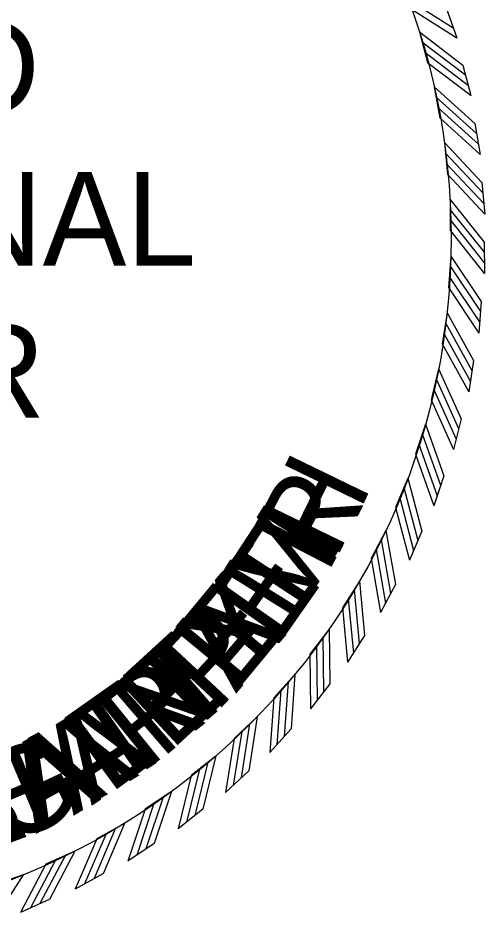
# Model space of a CAD drawing. Extents: x 18 to 14744716, y -5 to 1829144.
# Drawn here: x 17.7969 to 17.8525, y 10.8241 to 10.9324 of the extents above; entities that cross this region are included whole.
import ezdxf

# ---------------------------------------------------------------- set-up
doc = ezdxf.new("R2010")
doc.units = 0
for name, color, linetype in [('B_StampHSS', 7, 'Continuous'), ('B_StampJSB', 7, 'Continuous'), ('B_StampSCR', 7, 'Continuous'), ('B_StampSFH', 7, 'Continuous')]:
    doc.layers.add(name, color=color, linetype=linetype)

msp = doc.modelspace()

# ---------------------------------------------------------------- linework, layer by layer
at = {"layer": 'B_StampHSS'}
for p, q in [((17.84791, 10.93362), (17.84917, 10.93006)), ((17.84472, 10.93075), (17.84568, 10.9271)), ((17.8499, 10.9268), (17.85086, 10.92315)), ((17.84648, 10.9242), (17.84714, 10.92048)), ((17.85133, 10.91983), (17.85198, 10.91612)), ((17.8477, 10.91753), (17.84805, 10.91377)), ((17.85217, 10.91278), (17.85252, 10.90902)), ((17.84837, 10.91078), (17.8484, 10.90701)), ((17.85243, 10.90568), (17.85246, 10.90191)), ((17.84847, 10.904), (17.8482, 10.90023)), ((17.8521, 10.89858), (17.85182, 10.89482)), ((17.84802, 10.89724), (17.84743, 10.8935)), ((17.85118, 10.89153), (17.8506, 10.88781)), ((17.84701, 10.89053), (17.84611, 10.88686)), ((17.84545, 10.88393), (17.84425, 10.88035)), ((17.84969, 10.88458), (17.8488, 10.88092)), ((17.84334, 10.87748), (17.84186, 10.87401)), ((17.84763, 10.87778), (17.84643, 10.87421)), ((17.84072, 10.87123), (17.83895, 10.86789)), ((17.84501, 10.87117), (17.84353, 10.86771)), ((17.83758, 10.86522), (17.83554, 10.86203)), ((17.84186, 10.86481), (17.84009, 10.86147)), ((17.83396, 10.85948), (17.83167, 10.85648)), ((17.83819, 10.85872), (17.83615, 10.85555)), ((17.82988, 10.85406), (17.82735, 10.85126)), ((17.83403, 10.85296), (17.83174, 10.84996)), ((17.82536, 10.849), (17.82261, 10.84642)), ((17.82941, 10.84756), (17.82688, 10.84476)), ((17.82045, 10.84433), (17.81749, 10.84199)), ((17.82436, 10.84256), (17.82161, 10.83998)), ((17.81516, 10.84009), (17.81202, 10.83799)), ((17.81891, 10.83799), (17.81596, 10.83565)), ((17.80954, 10.83629), (17.80624, 10.83446)), ((17.81311, 10.83389), (17.80997, 10.8318)), ((17.80363, 10.83297), (17.80018, 10.83142)), ((17.79746, 10.83015), (17.7939, 10.82889)), ((17.80698, 10.83029), (17.80368, 10.82846)), ((17.80058, 10.8272), (17.79714, 10.82565))]:
    msp.add_line(p, q, dxfattribs=at)
for points in [[(17.84327, 10.93476), (17.84876, 10.93125)], [(17.84367, 10.93357), (17.84917, 10.93006)], [(17.84471, 10.93076), (17.8499, 10.9268)], [(17.84501, 10.92958), (17.8502, 10.92563)], [(17.84537, 10.92832), (17.85056, 10.92437)], [(17.84568, 10.9271), (17.85087, 10.92315)], [(17.84648, 10.92421), (17.85132, 10.91984)], [(17.84668, 10.92301), (17.85152, 10.91864)], [(17.84693, 10.92173), (17.85178, 10.91736)], [(17.84714, 10.92049), (17.85198, 10.91612)], [(17.8477, 10.91754), (17.85217, 10.91278)], [(17.8478, 10.91633), (17.85227, 10.91157)], [(17.84795, 10.91503), (17.85241, 10.91027)], [(17.84805, 10.91377), (17.85252, 10.90902)], [(17.84836, 10.91079), (17.85242, 10.90568)], [(17.84836, 10.90957), (17.85242, 10.90447)], [(17.84841, 10.90827), (17.85246, 10.90316)], [(17.84841, 10.90701), (17.85246, 10.9019)], [(17.84847, 10.90401), (17.85209, 10.89858)], [(17.84837, 10.9028), (17.85199, 10.89737)], [(17.8483, 10.90149), (17.85193, 10.89607)], [(17.8482, 10.90024), (17.85182, 10.89481)], [(17.84802, 10.89724), (17.85118, 10.89154)], [(17.84782, 10.89604), (17.85098, 10.89034)], [(17.84764, 10.89475), (17.8508, 10.88904)], [(17.84744, 10.89351), (17.8506, 10.8878)], [(17.84701, 10.89054), (17.84969, 10.88459)], [(17.84671, 10.88936), (17.84939, 10.88341)], [(17.84643, 10.88808), (17.84911, 10.88213)], [(17.84612, 10.88686), (17.8488, 10.88092)], [(17.84544, 10.88394), (17.84762, 10.87779)], [(17.84505, 10.88279), (17.84723, 10.87664)], [(17.84466, 10.88154), (17.84684, 10.87539)], [(17.84426, 10.88035), (17.84644, 10.8742)], [(17.84334, 10.87749), (17.84501, 10.87118)], [(17.84285, 10.87638), (17.84452, 10.87007)], [(17.84237, 10.87516), (17.84403, 10.86885)], [(17.84186, 10.87401), (17.84353, 10.8677)], [(17.84072, 10.87124), (17.84185, 10.86481)], [(17.84014, 10.87017), (17.84128, 10.86375)], [(17.83955, 10.869), (17.84069, 10.86257)], [(17.83895, 10.86789), (17.84009, 10.86147)], [(17.83758, 10.86522), (17.83819, 10.85873)], [(17.83692, 10.86421), (17.83752, 10.85771)], [(17.83624, 10.86309), (17.83684, 10.85659)], [(17.83555, 10.86204), (17.83615, 10.85554)], [(17.83396, 10.85949), (17.83403, 10.85296)], [(17.83322, 10.85853), (17.83328, 10.85201)], [(17.83167, 10.85648), (17.83174, 10.84996)], [(17.83244, 10.85747), (17.83251, 10.85095)], [(17.82906, 10.85318), (17.82859, 10.84667)], [(17.82988, 10.85407), (17.82941, 10.84756)], [(17.8282, 10.85219), (17.82773, 10.84568)], [(17.82735, 10.85126), (17.82688, 10.84476)], [(17.82537, 10.84901), (17.82436, 10.84257)], [(17.82447, 10.84819), (17.82347, 10.84174)], [(17.82354, 10.84727), (17.82253, 10.84083)], [(17.82261, 10.84642), (17.82161, 10.83998)], [(17.81949, 10.84359), (17.81795, 10.83725)], [(17.82045, 10.84434), (17.81891, 10.838)], [(17.81848, 10.84276), (17.81695, 10.83642)], [(17.81749, 10.84199), (17.81596, 10.83565)], [(17.81415, 10.83943), (17.81209, 10.83324)], [(17.81516, 10.84009), (17.81311, 10.8339)], [(17.81307, 10.83868), (17.81102, 10.83249)], [(17.81202, 10.83799), (17.80997, 10.8318)], [(17.80954, 10.83629), (17.80699, 10.83029)], [(17.80735, 10.83506), (17.80479, 10.82906)], [(17.80848, 10.83572), (17.80592, 10.82972)], [(17.80624, 10.83446), (17.80368, 10.82846)], [(17.80363, 10.83297), (17.80059, 10.8272)], [(17.80134, 10.83192), (17.79829, 10.82615)], [(17.80252, 10.83249), (17.79947, 10.82672)], [(17.80019, 10.83142), (17.79714, 10.82565)], [(17.79746, 10.83015), (17.79395, 10.82465)]]:
    msp.add_lwpolyline(points, dxfattribs=at)
at = {"layer": 'B_StampJSB'}
for p, q in [((17.84791, 10.93362), (17.84917, 10.93006)), ((17.84472, 10.93075), (17.84568, 10.9271)), ((17.8499, 10.9268), (17.85086, 10.92315)), ((17.84648, 10.9242), (17.84714, 10.92048)), ((17.85133, 10.91983), (17.85198, 10.91612)), ((17.8477, 10.91753), (17.84805, 10.91377)), ((17.85217, 10.91278), (17.85252, 10.90902)), ((17.84837, 10.91078), (17.8484, 10.90701)), ((17.85243, 10.90568), (17.85246, 10.90191)), ((17.84847, 10.904), (17.8482, 10.90023)), ((17.8521, 10.89858), (17.85182, 10.89482)), ((17.84802, 10.89724), (17.84743, 10.8935)), ((17.85118, 10.89153), (17.8506, 10.88781)), ((17.84701, 10.89053), (17.84611, 10.88686)), ((17.84545, 10.88393), (17.84425, 10.88035)), ((17.84969, 10.88458), (17.8488, 10.88092)), ((17.84334, 10.87748), (17.84186, 10.87401)), ((17.84763, 10.87778), (17.84643, 10.87421)), ((17.84072, 10.87123), (17.83895, 10.86789)), ((17.84501, 10.87117), (17.84353, 10.86771)), ((17.83758, 10.86522), (17.83554, 10.86203)), ((17.84186, 10.86481), (17.84009, 10.86147)), ((17.83396, 10.85948), (17.83167, 10.85648)), ((17.83819, 10.85872), (17.83615, 10.85555)), ((17.82988, 10.85406), (17.82735, 10.85126)), ((17.83403, 10.85296), (17.83174, 10.84996)), ((17.82536, 10.849), (17.82261, 10.84642)), ((17.82941, 10.84756), (17.82688, 10.84476)), ((17.82045, 10.84433), (17.81749, 10.84199)), ((17.82436, 10.84256), (17.82161, 10.83998)), ((17.81516, 10.84009), (17.81202, 10.83799)), ((17.81891, 10.83799), (17.81596, 10.83565)), ((17.80954, 10.83629), (17.80624, 10.83446)), ((17.81311, 10.83389), (17.80997, 10.8318)), ((17.80363, 10.83297), (17.80018, 10.83142)), ((17.79746, 10.83015), (17.7939, 10.82889)), ((17.80698, 10.83029), (17.80368, 10.82846)), ((17.80058, 10.8272), (17.79714, 10.82565))]:
    msp.add_line(p, q, dxfattribs=at)
for points in [[(17.84327, 10.93476), (17.84876, 10.93125)], [(17.84367, 10.93357), (17.84917, 10.93006)], [(17.84471, 10.93076), (17.8499, 10.9268)], [(17.84501, 10.92958), (17.8502, 10.92563)], [(17.84537, 10.92832), (17.85056, 10.92437)], [(17.84568, 10.9271), (17.85087, 10.92315)], [(17.84648, 10.92421), (17.85132, 10.91984)], [(17.84668, 10.92301), (17.85152, 10.91864)], [(17.84693, 10.92173), (17.85178, 10.91736)], [(17.84714, 10.92049), (17.85198, 10.91612)], [(17.8477, 10.91754), (17.85217, 10.91278)], [(17.8478, 10.91633), (17.85227, 10.91157)], [(17.84795, 10.91503), (17.85241, 10.91027)], [(17.84805, 10.91377), (17.85252, 10.90902)], [(17.84836, 10.91079), (17.85242, 10.90568)], [(17.84836, 10.90957), (17.85242, 10.90447)], [(17.84841, 10.90827), (17.85246, 10.90316)], [(17.84841, 10.90701), (17.85246, 10.9019)], [(17.84847, 10.90401), (17.85209, 10.89858)], [(17.84837, 10.9028), (17.85199, 10.89737)], [(17.8483, 10.90149), (17.85193, 10.89607)], [(17.8482, 10.90024), (17.85182, 10.89481)], [(17.84802, 10.89724), (17.85118, 10.89154)], [(17.84782, 10.89604), (17.85098, 10.89034)], [(17.84764, 10.89475), (17.8508, 10.88904)], [(17.84744, 10.89351), (17.8506, 10.8878)], [(17.84701, 10.89054), (17.84969, 10.88459)], [(17.84671, 10.88936), (17.84939, 10.88341)], [(17.84643, 10.88808), (17.84911, 10.88213)], [(17.84612, 10.88686), (17.8488, 10.88092)], [(17.84544, 10.88394), (17.84762, 10.87779)], [(17.84505, 10.88279), (17.84723, 10.87664)], [(17.84466, 10.88154), (17.84684, 10.87539)], [(17.84426, 10.88035), (17.84644, 10.8742)], [(17.84334, 10.87749), (17.84501, 10.87118)], [(17.84285, 10.87638), (17.84452, 10.87007)], [(17.84237, 10.87516), (17.84403, 10.86885)], [(17.84186, 10.87401), (17.84353, 10.8677)], [(17.84072, 10.87124), (17.84185, 10.86481)], [(17.84014, 10.87017), (17.84128, 10.86375)], [(17.83955, 10.869), (17.84069, 10.86257)], [(17.83895, 10.86789), (17.84009, 10.86147)], [(17.83758, 10.86522), (17.83819, 10.85873)], [(17.83692, 10.86421), (17.83752, 10.85771)], [(17.83624, 10.86309), (17.83684, 10.85659)], [(17.83555, 10.86204), (17.83615, 10.85554)], [(17.83396, 10.85949), (17.83403, 10.85296)], [(17.83322, 10.85853), (17.83328, 10.85201)], [(17.83167, 10.85648), (17.83174, 10.84996)], [(17.83244, 10.85747), (17.83251, 10.85095)], [(17.82906, 10.85318), (17.82859, 10.84667)], [(17.82988, 10.85407), (17.82941, 10.84756)], [(17.8282, 10.85219), (17.82773, 10.84568)], [(17.82735, 10.85126), (17.82688, 10.84476)], [(17.82537, 10.84901), (17.82436, 10.84257)], [(17.82447, 10.84819), (17.82347, 10.84174)], [(17.82354, 10.84727), (17.82253, 10.84083)], [(17.82261, 10.84642), (17.82161, 10.83998)], [(17.81949, 10.84359), (17.81795, 10.83725)], [(17.82045, 10.84434), (17.81891, 10.838)], [(17.81848, 10.84276), (17.81695, 10.83642)], [(17.81749, 10.84199), (17.81596, 10.83565)], [(17.81415, 10.83943), (17.81209, 10.83324)], [(17.81516, 10.84009), (17.81311, 10.8339)], [(17.81307, 10.83868), (17.81102, 10.83249)], [(17.81202, 10.83799), (17.80997, 10.8318)], [(17.80954, 10.83629), (17.80699, 10.83029)], [(17.80735, 10.83506), (17.80479, 10.82906)], [(17.80848, 10.83572), (17.80592, 10.82972)], [(17.80624, 10.83446), (17.80368, 10.82846)], [(17.80363, 10.83297), (17.80059, 10.8272)], [(17.80134, 10.83192), (17.79829, 10.82615)], [(17.80252, 10.83249), (17.79947, 10.82672)], [(17.80019, 10.83142), (17.79714, 10.82565)], [(17.79746, 10.83015), (17.79395, 10.82465)]]:
    msp.add_lwpolyline(points, dxfattribs=at)
msp.add_circle((17.76645, 10.90612), 0.08205, dxfattribs=at)
at = {"layer": 'B_StampSCR'}
for p, q in [((17.84791, 10.93362), (17.84917, 10.93006)), ((17.84472, 10.93075), (17.84568, 10.9271)), ((17.8499, 10.9268), (17.85086, 10.92315)), ((17.84648, 10.9242), (17.84714, 10.92048)), ((17.85133, 10.91983), (17.85198, 10.91612)), ((17.8477, 10.91753), (17.84805, 10.91377)), ((17.85217, 10.91278), (17.85252, 10.90902)), ((17.84837, 10.91078), (17.8484, 10.90701)), ((17.85243, 10.90568), (17.85246, 10.90191)), ((17.84847, 10.904), (17.8482, 10.90023)), ((17.8521, 10.89858), (17.85182, 10.89482)), ((17.84802, 10.89724), (17.84743, 10.8935)), ((17.85118, 10.89153), (17.8506, 10.88781)), ((17.84701, 10.89053), (17.84611, 10.88686)), ((17.84545, 10.88393), (17.84425, 10.88035)), ((17.84969, 10.88458), (17.8488, 10.88092)), ((17.84334, 10.87748), (17.84186, 10.87401)), ((17.84763, 10.87778), (17.84643, 10.87421)), ((17.84072, 10.87123), (17.83895, 10.86789)), ((17.84501, 10.87117), (17.84353, 10.86771)), ((17.83758, 10.86522), (17.83554, 10.86203)), ((17.84186, 10.86481), (17.84009, 10.86147)), ((17.83396, 10.85948), (17.83167, 10.85648)), ((17.83819, 10.85872), (17.83615, 10.85555)), ((17.82988, 10.85406), (17.82735, 10.85126)), ((17.83403, 10.85296), (17.83174, 10.84996)), ((17.82536, 10.849), (17.82261, 10.84642)), ((17.82941, 10.84756), (17.82688, 10.84476)), ((17.82045, 10.84433), (17.81749, 10.84199)), ((17.82436, 10.84256), (17.82161, 10.83998)), ((17.81516, 10.84009), (17.81202, 10.83799)), ((17.81891, 10.83799), (17.81596, 10.83565)), ((17.80954, 10.83629), (17.80624, 10.83446)), ((17.81311, 10.83389), (17.80997, 10.8318)), ((17.80363, 10.83297), (17.80018, 10.83142)), ((17.79746, 10.83015), (17.7939, 10.82889)), ((17.80698, 10.83029), (17.80368, 10.82846)), ((17.80058, 10.8272), (17.79714, 10.82565))]:
    msp.add_line(p, q, dxfattribs=at)
for points in [[(17.84327, 10.93476), (17.84876, 10.93125)], [(17.84367, 10.93357), (17.84917, 10.93006)], [(17.84471, 10.93076), (17.8499, 10.9268)], [(17.84501, 10.92958), (17.8502, 10.92563)], [(17.84537, 10.92832), (17.85056, 10.92437)], [(17.84568, 10.9271), (17.85087, 10.92315)], [(17.84648, 10.92421), (17.85132, 10.91984)], [(17.84668, 10.92301), (17.85152, 10.91864)], [(17.84693, 10.92173), (17.85178, 10.91736)], [(17.84714, 10.92049), (17.85198, 10.91612)], [(17.8477, 10.91754), (17.85217, 10.91278)], [(17.8478, 10.91633), (17.85227, 10.91157)], [(17.84795, 10.91503), (17.85241, 10.91027)], [(17.84805, 10.91377), (17.85252, 10.90902)], [(17.84836, 10.91079), (17.85242, 10.90568)], [(17.84836, 10.90957), (17.85242, 10.90447)], [(17.84841, 10.90827), (17.85246, 10.90316)], [(17.84841, 10.90701), (17.85246, 10.9019)], [(17.84847, 10.90401), (17.85209, 10.89858)], [(17.84837, 10.9028), (17.85199, 10.89737)], [(17.8483, 10.90149), (17.85193, 10.89607)], [(17.8482, 10.90024), (17.85182, 10.89481)], [(17.84802, 10.89724), (17.85118, 10.89154)], [(17.84782, 10.89604), (17.85098, 10.89034)], [(17.84764, 10.89475), (17.8508, 10.88904)], [(17.84744, 10.89351), (17.8506, 10.8878)], [(17.84701, 10.89054), (17.84969, 10.88459)], [(17.84671, 10.88936), (17.84939, 10.88341)], [(17.84643, 10.88808), (17.84911, 10.88213)], [(17.84612, 10.88686), (17.8488, 10.88092)], [(17.84544, 10.88394), (17.84762, 10.87779)], [(17.84505, 10.88279), (17.84723, 10.87664)], [(17.84466, 10.88154), (17.84684, 10.87539)], [(17.84426, 10.88035), (17.84644, 10.8742)], [(17.84334, 10.87749), (17.84501, 10.87118)], [(17.84285, 10.87638), (17.84452, 10.87007)], [(17.84237, 10.87516), (17.84403, 10.86885)], [(17.84186, 10.87401), (17.84353, 10.8677)], [(17.84072, 10.87124), (17.84185, 10.86481)], [(17.84014, 10.87017), (17.84128, 10.86375)], [(17.83955, 10.869), (17.84069, 10.86257)], [(17.83895, 10.86789), (17.84009, 10.86147)], [(17.83758, 10.86522), (17.83819, 10.85873)], [(17.83692, 10.86421), (17.83752, 10.85771)], [(17.83624, 10.86309), (17.83684, 10.85659)], [(17.83555, 10.86204), (17.83615, 10.85554)], [(17.83396, 10.85949), (17.83403, 10.85296)], [(17.83322, 10.85853), (17.83328, 10.85201)], [(17.83167, 10.85648), (17.83174, 10.84996)], [(17.83244, 10.85747), (17.83251, 10.85095)], [(17.82906, 10.85318), (17.82859, 10.84667)], [(17.82988, 10.85407), (17.82941, 10.84756)], [(17.8282, 10.85219), (17.82773, 10.84568)], [(17.82735, 10.85126), (17.82688, 10.84476)], [(17.82537, 10.84901), (17.82436, 10.84257)], [(17.82447, 10.84819), (17.82347, 10.84174)], [(17.82354, 10.84727), (17.82253, 10.84083)], [(17.82261, 10.84642), (17.82161, 10.83998)], [(17.81949, 10.84359), (17.81795, 10.83725)], [(17.82045, 10.84434), (17.81891, 10.838)], [(17.81848, 10.84276), (17.81695, 10.83642)], [(17.81749, 10.84199), (17.81596, 10.83565)], [(17.81415, 10.83943), (17.81209, 10.83324)], [(17.81516, 10.84009), (17.81311, 10.8339)], [(17.81307, 10.83868), (17.81102, 10.83249)], [(17.81202, 10.83799), (17.80997, 10.8318)], [(17.80954, 10.83629), (17.80699, 10.83029)], [(17.80735, 10.83506), (17.80479, 10.82906)], [(17.80848, 10.83572), (17.80592, 10.82972)], [(17.80624, 10.83446), (17.80368, 10.82846)], [(17.80363, 10.83297), (17.80059, 10.8272)], [(17.80134, 10.83192), (17.79829, 10.82615)], [(17.80252, 10.83249), (17.79947, 10.82672)], [(17.80019, 10.83142), (17.79714, 10.82565)], [(17.79746, 10.83015), (17.79395, 10.82465)]]:
    msp.add_lwpolyline(points, dxfattribs=at)
at = {"layer": 'B_StampSFH'}
for p, q in [((17.84791, 10.93362), (17.84917, 10.93006)), ((17.84472, 10.93075), (17.84568, 10.9271)), ((17.8499, 10.9268), (17.85086, 10.92315)), ((17.84648, 10.9242), (17.84714, 10.92048)), ((17.85133, 10.91983), (17.85198, 10.91612)), ((17.8477, 10.91753), (17.84805, 10.91377)), ((17.85217, 10.91278), (17.85252, 10.90902)), ((17.84837, 10.91078), (17.8484, 10.90701)), ((17.85243, 10.90568), (17.85246, 10.90191)), ((17.84847, 10.904), (17.8482, 10.90023)), ((17.8521, 10.89858), (17.85182, 10.89482)), ((17.84802, 10.89724), (17.84743, 10.8935)), ((17.85118, 10.89153), (17.8506, 10.88781)), ((17.84701, 10.89053), (17.84611, 10.88686)), ((17.84545, 10.88393), (17.84425, 10.88035)), ((17.84969, 10.88458), (17.8488, 10.88092)), ((17.84334, 10.87748), (17.84186, 10.87401)), ((17.84763, 10.87778), (17.84643, 10.87421)), ((17.84072, 10.87123), (17.83895, 10.86789)), ((17.84501, 10.87117), (17.84353, 10.86771)), ((17.83758, 10.86522), (17.83554, 10.86203)), ((17.84186, 10.86481), (17.84009, 10.86147)), ((17.83396, 10.85948), (17.83167, 10.85648)), ((17.83819, 10.85872), (17.83615, 10.85555)), ((17.82988, 10.85406), (17.82735, 10.85126)), ((17.83403, 10.85296), (17.83174, 10.84996)), ((17.82536, 10.849), (17.82261, 10.84642)), ((17.82941, 10.84756), (17.82688, 10.84476)), ((17.82045, 10.84433), (17.81749, 10.84199)), ((17.82436, 10.84256), (17.82161, 10.83998)), ((17.81516, 10.84009), (17.81202, 10.83799)), ((17.81891, 10.83799), (17.81596, 10.83565)), ((17.80954, 10.83629), (17.80624, 10.83446)), ((17.81311, 10.83389), (17.80997, 10.8318)), ((17.80363, 10.83297), (17.80018, 10.83142)), ((17.79746, 10.83015), (17.7939, 10.82889)), ((17.80698, 10.83029), (17.80368, 10.82846)), ((17.80058, 10.8272), (17.79714, 10.82565))]:
    msp.add_line(p, q, dxfattribs=at)
for points in [[(17.84327, 10.93476), (17.84876, 10.93125)], [(17.84367, 10.93357), (17.84917, 10.93006)], [(17.84471, 10.93076), (17.8499, 10.9268)], [(17.84501, 10.92958), (17.8502, 10.92563)], [(17.84537, 10.92832), (17.85056, 10.92437)], [(17.84568, 10.9271), (17.85087, 10.92315)], [(17.84648, 10.92421), (17.85132, 10.91984)], [(17.84668, 10.92301), (17.85152, 10.91864)], [(17.84693, 10.92173), (17.85178, 10.91736)], [(17.84714, 10.92049), (17.85198, 10.91612)], [(17.8477, 10.91754), (17.85217, 10.91278)], [(17.8478, 10.91633), (17.85227, 10.91157)], [(17.84795, 10.91503), (17.85241, 10.91027)], [(17.84805, 10.91377), (17.85252, 10.90902)], [(17.84836, 10.91079), (17.85242, 10.90568)], [(17.84836, 10.90957), (17.85242, 10.90447)], [(17.84841, 10.90827), (17.85246, 10.90316)], [(17.84841, 10.90701), (17.85246, 10.9019)], [(17.84847, 10.90401), (17.85209, 10.89858)], [(17.84837, 10.9028), (17.85199, 10.89737)], [(17.8483, 10.90149), (17.85193, 10.89607)], [(17.8482, 10.90024), (17.85182, 10.89481)], [(17.84802, 10.89724), (17.85118, 10.89154)], [(17.84782, 10.89604), (17.85098, 10.89034)], [(17.84764, 10.89475), (17.8508, 10.88904)], [(17.84744, 10.89351), (17.8506, 10.8878)], [(17.84701, 10.89054), (17.84969, 10.88459)], [(17.84671, 10.88936), (17.84939, 10.88341)], [(17.84643, 10.88808), (17.84911, 10.88213)], [(17.84612, 10.88686), (17.8488, 10.88092)], [(17.84544, 10.88394), (17.84762, 10.87779)], [(17.84505, 10.88279), (17.84723, 10.87664)], [(17.84466, 10.88154), (17.84684, 10.87539)], [(17.84426, 10.88035), (17.84644, 10.8742)], [(17.84334, 10.87749), (17.84501, 10.87118)], [(17.84285, 10.87638), (17.84452, 10.87007)], [(17.84237, 10.87516), (17.84403, 10.86885)], [(17.84186, 10.87401), (17.84353, 10.8677)], [(17.84072, 10.87124), (17.84185, 10.86481)], [(17.84014, 10.87017), (17.84128, 10.86375)], [(17.83955, 10.869), (17.84069, 10.86257)], [(17.83895, 10.86789), (17.84009, 10.86147)], [(17.83758, 10.86522), (17.83819, 10.85873)], [(17.83692, 10.86421), (17.83752, 10.85771)], [(17.83624, 10.86309), (17.83684, 10.85659)], [(17.83555, 10.86204), (17.83615, 10.85554)], [(17.83396, 10.85949), (17.83403, 10.85296)], [(17.83322, 10.85853), (17.83328, 10.85201)], [(17.83167, 10.85648), (17.83174, 10.84996)], [(17.83244, 10.85747), (17.83251, 10.85095)], [(17.82906, 10.85318), (17.82859, 10.84667)], [(17.82988, 10.85407), (17.82941, 10.84756)], [(17.8282, 10.85219), (17.82773, 10.84568)], [(17.82735, 10.85126), (17.82688, 10.84476)], [(17.82537, 10.84901), (17.82436, 10.84257)], [(17.82447, 10.84819), (17.82347, 10.84174)], [(17.82354, 10.84727), (17.82253, 10.84083)], [(17.82261, 10.84642), (17.82161, 10.83998)], [(17.81949, 10.84359), (17.81795, 10.83725)], [(17.82045, 10.84434), (17.81891, 10.838)], [(17.81848, 10.84276), (17.81695, 10.83642)], [(17.81749, 10.84199), (17.81596, 10.83565)], [(17.81415, 10.83943), (17.81209, 10.83324)], [(17.81516, 10.84009), (17.81311, 10.8339)], [(17.81307, 10.83868), (17.81102, 10.83249)], [(17.81202, 10.83799), (17.80997, 10.8318)], [(17.80954, 10.83629), (17.80699, 10.83029)], [(17.80735, 10.83506), (17.80479, 10.82906)], [(17.80848, 10.83572), (17.80592, 10.82972)], [(17.80624, 10.83446), (17.80368, 10.82846)], [(17.80363, 10.83297), (17.80059, 10.8272)], [(17.80134, 10.83192), (17.79829, 10.82615)], [(17.80252, 10.83249), (17.79947, 10.82672)], [(17.80019, 10.83142), (17.79714, 10.82565)], [(17.79746, 10.83015), (17.79395, 10.82465)]]:
    msp.add_lwpolyline(points, dxfattribs=at)

# ---------------------------------------------------------------- texts
at = {"layer": 'B_StampHSS'}
for s, height, p in [('LICENSED', 0.011194, (17.72458, 10.92096)), ('PROFESSIONAL', 0.0111938, (17.70165, 10.90284)), ('ENGINEER', 0.011194, (17.72191, 10.88472))]:
    msp.add_text(s, height=height, dxfattribs=at).set_placement(p)
for s, rotation, p in [('M', 58.0941, (17.8295, 10.85986)), ('E', 50.4419, (17.82277, 10.85187)), ('E', 42.7897, (17.81505, 10.84485)), ('L', 36.2307, (17.80773, 10.8397)), ('A', 28.9428, (17.79897, 10.835)), ('S', 21.655, (17.78968, 10.83144))]:
    msp.add_text(s, height=0.01042, rotation=rotation, dxfattribs=at).set_placement(p)
at = {"layer": 'B_StampJSB'}
for s, height, p in [('LICENSED', 0.011194, (17.72458, 10.92096)), ('PROFESSIONAL', 0.0111938, (17.70165, 10.90284)), ('ENGINEER', 0.011194, (17.72191, 10.88472))]:
    msp.add_text(s, height=height, dxfattribs=at).set_placement(p)
for s, rotation, p in [('Y', 49.8075, (17.82338, 10.85282)), ('T', 42.5097, (17.81615, 10.84602)), ('T', 35.2119, (17.80811, 10.84019)), ('A', 27.9141, (17.7994, 10.83543)), ('E', 20.2514, (17.78968, 10.83167))]:
    msp.add_text(s, height=0.01042, rotation=rotation, dxfattribs=at).set_placement(p)
at = {"layer": 'B_StampSCR'}
for s, height, p in [('LICENSED', 0.011194, (17.72458, 10.92096)), ('PROFESSIONAL', 0.0111938, (17.70165, 10.90284)), ('ENGINEER', 0.011194, (17.72191, 10.88472))]:
    msp.add_text(s, height=height, dxfattribs=at).set_placement(p)
for s, rotation, p in [('H', 64.101, (17.83473, 10.86761)), ('T', 56.805, (17.82929, 10.8593)), ('A', 49.509, (17.82284, 10.85174)), ('N', 40.7538, (17.81391, 10.84385)), ('A', 33.4578, (17.80562, 10.83837)), ('G', 25.0674, (17.79533, 10.83343))]:
    msp.add_text(s, height=0.01042, rotation=rotation, dxfattribs=at).set_placement(p)
at = {"layer": 'B_StampSFH'}
for s, height, p in [('LICENSED', 0.011194, (17.72458, 10.92096)), ('PROFESSIONAL', 0.0111938, (17.70165, 10.90284)), ('ENGINEER', 0.011194, (17.72191, 10.88472))]:
    msp.add_text(s, height=height, dxfattribs=at).set_placement(p)
for s, rotation, p in [('R', 62.6418, (17.83372, 10.8659)), ('E', 54.981, (17.82777, 10.85734)), ('P', 46.9554, (17.82036, 10.8493)), ('R', 38.9298, (17.81191, 10.84238)), ('A', 31.6338, (17.80345, 10.83717)), ('H', 22.8786, (17.79253, 10.8324))]:
    msp.add_text(s, height=0.01042, rotation=rotation, dxfattribs=at).set_placement(p)

doc.saveas('drawing.dxf')
